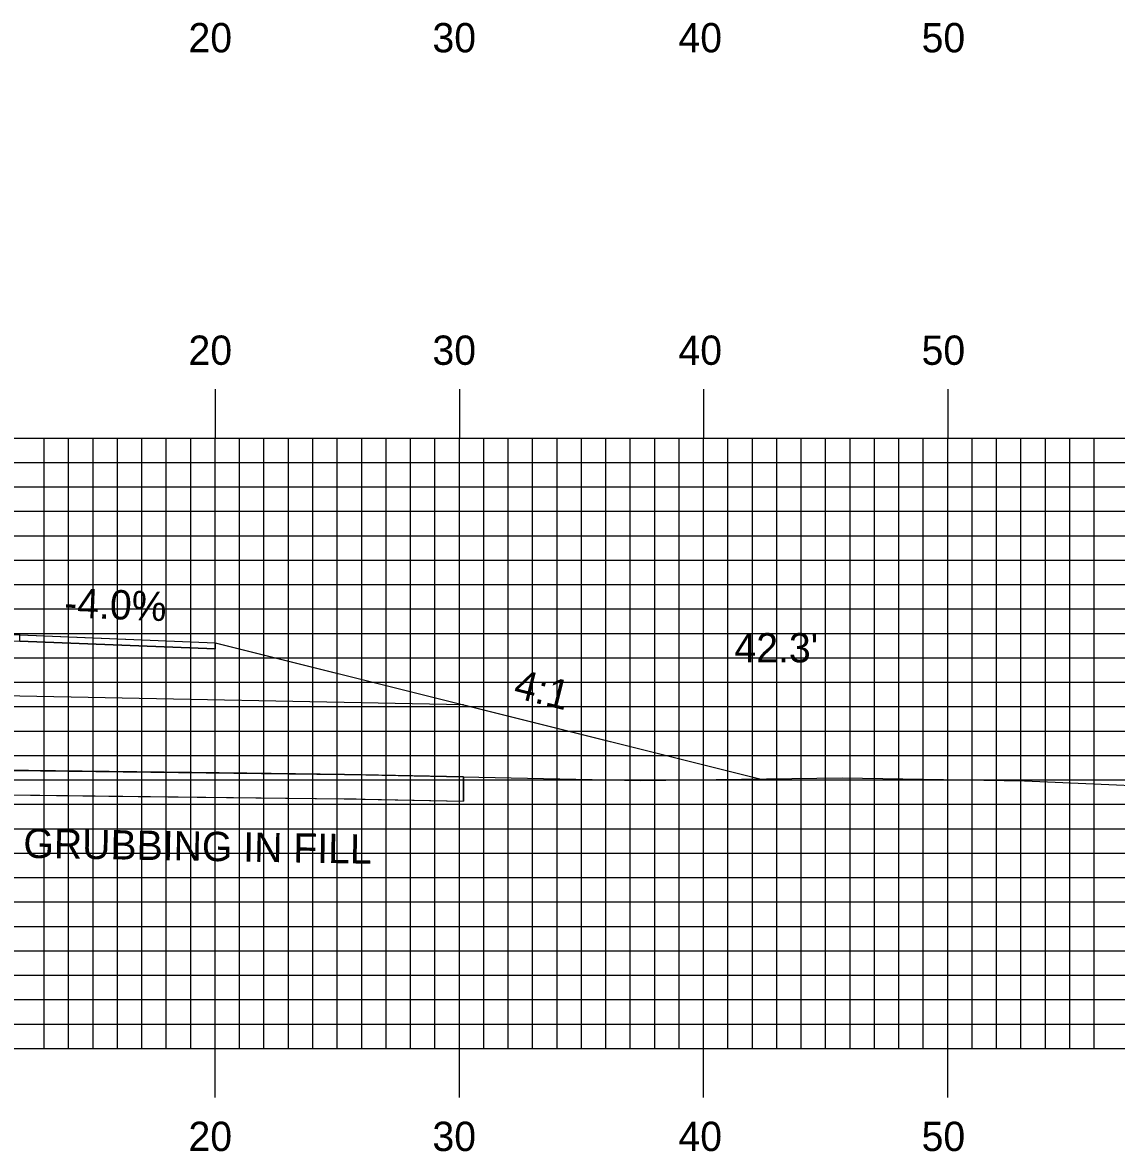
# Model space of a CAD drawing. Extents: x 1771629 to 1771972, y 442591 to 442811.
# Drawn here: x 1771806.69 to 1771851.49, y 442649.45 to 442695.68 of the extents above; entities that cross this region are included whole.
import ezdxf

# ---------------------------------------------------------------- set-up
doc = ezdxf.new("R2010")
doc.units = 0
for name, color, linetype in [('ANNOTATION', 7, 'Continuous'), ('D_Roadway_Centerline', 7, 'Continuous'), ('D_Roadway_Edge_Shoulder', 7, 'Continuous'), ('D_Roadway_SlopeLines', 7, 'Continuous'), ('D_Roadway_SubGrade', 7, 'Continuous'), ('D_Text_Standard', 7, 'Continuous'), ('GRUBBING IN FILL', 7, 'Continuous'), ('H_V ANNOTATION', 7, 'Continuous'), ('MAJOR', 7, 'Continuous'), ('MINOR', 7, 'Continuous'), ('S_Roadway_Centerline', 7, 'Continuous')]:
    doc.layers.add(name, color=color, linetype=linetype)

msp = doc.modelspace()

# ---------------------------------------------------------------- linework, layer by layer
at = {"layer": 'D_Roadway_Centerline'}
msp.add_lwpolyline([(1771759.249, 442666.447), (1771762.58, 442667.28), (1771764.404, 442667.736), (1771764.407, 442667.736), (1771764.42, 442667.74), (1771772.599, 442669.785), (1771774.581, 442670.28), (1771774.583, 442670.28), (1771778.655, 442670.443), (1771782.581, 442670.6), (1771782.585, 442670.6), (1771785.333, 442670.655), (1771794.58, 442670.84), (1771806.564, 442670.601), (1771806.581, 442670.6), (1771806.592, 442670.6), (1771814.581, 442670.28), (1771814.588, 442670.278), (1771822.681, 442668.255), (1771824.754, 442667.736), (1771824.757, 442667.736), (1771836.89, 442664.702)], dxfattribs=at)
at = {"layer": 'D_Roadway_Edge_Shoulder'}
msp.add_lwpolyline([(1771806.581, 442670.6), (1771814.581, 442670.28), (1771814.581, 442670.03), (1771806.581, 442670.35)], close=True, dxfattribs=at)
at = {"layer": 'D_Roadway_SlopeLines'}
msp.add_lwpolyline([(1771814.581, 442670.28), (1771824.754, 442667.736), (1771836.89, 442664.702)], dxfattribs=at)
at = {"layer": 'D_Roadway_SubGrade'}
msp.add_lwpolyline([(1771782.581, 442668.1), (1771764.407, 442667.736), (1771774.581, 442670.28), (1771774.581, 442670.03), (1771782.581, 442670.35), (1771794.58, 442670.59), (1771806.581, 442670.35), (1771814.581, 442670.03), (1771814.581, 442670.28), (1771824.754, 442667.736), (1771806.581, 442668.1), (1771794.58, 442668.34)], close=True, dxfattribs=at)
at = {"layer": 'GRUBBING IN FILL'}
msp.add_line((1771824.754, 442664.79), (1771824.754, 442663.79), dxfattribs=at)
msp.add_line((1771824.754, 442664.79), (1771824.754, 442663.79), dxfattribs=at)
msp.add_lwpolyline([(1771764.407, 442665.173), (1771773.996, 442664.851), (1771780.873, 442664.574), (1771783.959, 442664.55), (1771791.195, 442664.327), (1771800.594, 442664.12), (1771819.869, 442663.889), (1771820.358, 442663.884), (1771820.72, 442663.874), (1771824.754, 442663.79)], dxfattribs=at)
msp.add_lwpolyline([(1771764.407, 442665.173), (1771773.996, 442664.851), (1771780.873, 442664.574), (1771783.959, 442664.55), (1771791.195, 442664.327), (1771800.594, 442664.12), (1771819.869, 442663.889), (1771820.358, 442663.884), (1771820.72, 442663.874), (1771824.754, 442663.79)], dxfattribs=at)
msp.add_lwpolyline([(1771824.754, 442664.79), (1771819.881, 442664.889), (1771815.873, 442664.937), (1771810.246, 442665.005), (1771805.849, 442665.057), (1771800.611, 442665.12), (1771796.705, 442665.206), (1771794.58, 442665.253), (1771794.58, 442664.253), (1771800.594, 442664.12), (1771810.232, 442664.005), (1771819.869, 442663.889), (1771824.754, 442663.79)], close=True, dxfattribs=at)
msp.add_lwpolyline([(1771824.754, 442664.79), (1771819.881, 442664.889), (1771815.873, 442664.937), (1771810.246, 442665.005), (1771805.849, 442665.057), (1771800.611, 442665.12), (1771796.705, 442665.206), (1771794.58, 442665.253), (1771794.58, 442664.253), (1771800.594, 442664.12), (1771810.232, 442664.005), (1771819.869, 442663.889), (1771824.754, 442663.79)], close=True, dxfattribs=at)
at = {"layer": 'MAJOR'}
for p, q in [((1771814.58, 442680.669), (1771814.58, 442678.665)), ((1771824.58, 442680.669), (1771824.58, 442678.665)), ((1771834.58, 442680.669), (1771834.58, 442678.665)), ((1771844.58, 442680.669), (1771844.58, 442678.665)), ((1771654.58, 442678.665), (1771934.58, 442678.665)), ((1771654.58, 442678.665), (1771934.58, 442678.665)), ((1771814.58, 442653.665), (1771814.58, 442678.665)), ((1771824.58, 442653.665), (1771824.58, 442678.665)), ((1771834.58, 442653.665), (1771834.58, 442678.665)), ((1771844.58, 442653.665), (1771844.58, 442678.665)), ((1771654.58, 442673.665), (1771934.58, 442673.665)), ((1771654.58, 442668.665), (1771934.58, 442668.665)), ((1771654.58, 442663.665), (1771934.58, 442663.665)), ((1771654.58, 442658.665), (1771934.58, 442658.665)), ((1771654.58, 442653.665), (1771934.58, 442653.665)), ((1771654.58, 442653.665), (1771934.58, 442653.665)), ((1771814.58, 442651.661), (1771814.58, 442653.665)), ((1771824.58, 442651.661), (1771824.58, 442653.665)), ((1771834.58, 442651.661), (1771834.58, 442653.665)), ((1771844.58, 442651.661), (1771844.58, 442653.665))]:
    msp.add_line(p, q, dxfattribs=at)
at = {"layer": 'MINOR'}
for p, q in [((1771807.58, 442653.665), (1771807.58, 442678.665)), ((1771808.58, 442653.665), (1771808.58, 442678.665)), ((1771809.58, 442653.665), (1771809.58, 442678.665)), ((1771810.58, 442653.665), (1771810.58, 442678.665)), ((1771811.58, 442653.665), (1771811.58, 442678.665)), ((1771812.58, 442653.665), (1771812.58, 442678.665)), ((1771813.58, 442653.665), (1771813.58, 442678.665)), ((1771815.58, 442653.665), (1771815.58, 442678.665)), ((1771816.58, 442653.665), (1771816.58, 442678.665)), ((1771817.58, 442653.665), (1771817.58, 442678.665)), ((1771818.58, 442653.665), (1771818.58, 442678.665)), ((1771819.58, 442653.665), (1771819.58, 442678.665)), ((1771820.58, 442653.665), (1771820.58, 442678.665)), ((1771821.58, 442653.665), (1771821.58, 442678.665)), ((1771822.58, 442653.665), (1771822.58, 442678.665)), ((1771823.58, 442653.665), (1771823.58, 442678.665)), ((1771825.58, 442653.665), (1771825.58, 442678.665)), ((1771826.58, 442653.665), (1771826.58, 442678.665)), ((1771827.58, 442653.665), (1771827.58, 442678.665)), ((1771828.58, 442653.665), (1771828.58, 442678.665)), ((1771829.58, 442653.665), (1771829.58, 442678.665)), ((1771830.58, 442653.665), (1771830.58, 442678.665)), ((1771831.58, 442653.665), (1771831.58, 442678.665)), ((1771832.58, 442653.665), (1771832.58, 442678.665)), ((1771833.58, 442653.665), (1771833.58, 442678.665)), ((1771835.58, 442653.665), (1771835.58, 442678.665)), ((1771836.58, 442653.665), (1771836.58, 442678.665)), ((1771837.58, 442653.665), (1771837.58, 442678.665)), ((1771838.58, 442653.665), (1771838.58, 442678.665)), ((1771839.58, 442653.665), (1771839.58, 442678.665)), ((1771840.58, 442653.665), (1771840.58, 442678.665)), ((1771841.58, 442653.665), (1771841.58, 442678.665)), ((1771842.58, 442653.665), (1771842.58, 442678.665)), ((1771843.58, 442653.665), (1771843.58, 442678.665)), ((1771845.58, 442653.665), (1771845.58, 442678.665)), ((1771846.58, 442653.665), (1771846.58, 442678.665)), ((1771847.58, 442653.665), (1771847.58, 442678.665)), ((1771848.58, 442653.665), (1771848.58, 442678.665)), ((1771849.58, 442653.665), (1771849.58, 442678.665)), ((1771850.58, 442653.665), (1771850.58, 442678.665)), ((1771654.58, 442677.665), (1771934.58, 442677.665)), ((1771654.58, 442676.665), (1771934.58, 442676.665)), ((1771654.58, 442675.665), (1771934.58, 442675.665)), ((1771654.58, 442674.665), (1771934.58, 442674.665)), ((1771654.58, 442672.665), (1771934.58, 442672.665)), ((1771654.58, 442671.665), (1771934.58, 442671.665)), ((1771654.58, 442670.665), (1771934.58, 442670.665)), ((1771654.58, 442669.665), (1771934.58, 442669.665)), ((1771654.58, 442667.665), (1771934.58, 442667.665)), ((1771654.58, 442666.665), (1771934.58, 442666.665)), ((1771654.58, 442665.665), (1771934.58, 442665.665)), ((1771654.58, 442664.665), (1771934.58, 442664.665)), ((1771654.58, 442662.665), (1771934.58, 442662.665)), ((1771654.58, 442661.665), (1771934.58, 442661.665)), ((1771654.58, 442660.665), (1771934.58, 442660.665)), ((1771654.58, 442659.665), (1771934.58, 442659.665)), ((1771654.58, 442657.665), (1771934.58, 442657.665)), ((1771654.58, 442656.665), (1771934.58, 442656.665)), ((1771654.58, 442655.665), (1771934.58, 442655.665)), ((1771654.58, 442654.665), (1771934.58, 442654.665))]:
    msp.add_line(p, q, dxfattribs=at)
at = {"layer": 'S_Roadway_Centerline'}
msp.add_lwpolyline([(1771739.704, 442666.461), (1771749.349, 442666.644), (1771759.215, 442666.45), (1771761.237, 442666.272), (1771764.075, 442666.185), (1771774.033, 442665.85), (1771780.897, 442665.574), (1771783.979, 442665.55), (1771791.222, 442665.327), (1771800.611, 442665.12), (1771819.881, 442664.889), (1771820.378, 442664.884), (1771820.744, 442664.873), (1771832.005, 442664.639), (1771840.262, 442664.746), (1771847.726, 442664.622), (1771855.867, 442664.271)], dxfattribs=at)

# ---------------------------------------------------------------- texts
at = {"layer": 'ANNOTATION'}
for s, rotation, p in [('-4.0%', 357.7094, (1771808.378, 442671.33)), ('4:1', 345.9605, (1771826.746, 442668.053))]:
    msp.add_text(s, height=1.2, rotation=rotation, dxfattribs=at).set_placement(p)
at = {"layer": 'D_Text_Standard'}
msp.add_text("42.3'", height=1.2, dxfattribs=at).set_placement((1771835.846, 442669.478))
at = {"layer": 'GRUBBING IN FILL'}
msp.add_text('GRUBBING IN FILL', height=1.2, rotation=359.0192, dxfattribs=at).set_placement((1771806.718, 442661.474))
at = {"layer": 'H_V ANNOTATION'}
for s, p in [('20', (1771813.488, 442694.465)), ('30', (1771823.478, 442694.465)), ('40', (1771833.553, 442694.465)), ('50', (1771843.51, 442694.465)), ('20', (1771813.488, 442681.665)), ('30', (1771823.478, 442681.665)), ('40', (1771833.553, 442681.665)), ('50', (1771843.51, 442681.665)), ('20', (1771813.488, 442649.465)), ('30', (1771823.478, 442649.465)), ('40', (1771833.553, 442649.465)), ('50', (1771843.51, 442649.465))]:
    msp.add_text(s, height=1.2, dxfattribs=at).set_placement(p)

doc.saveas('drawing.dxf')
